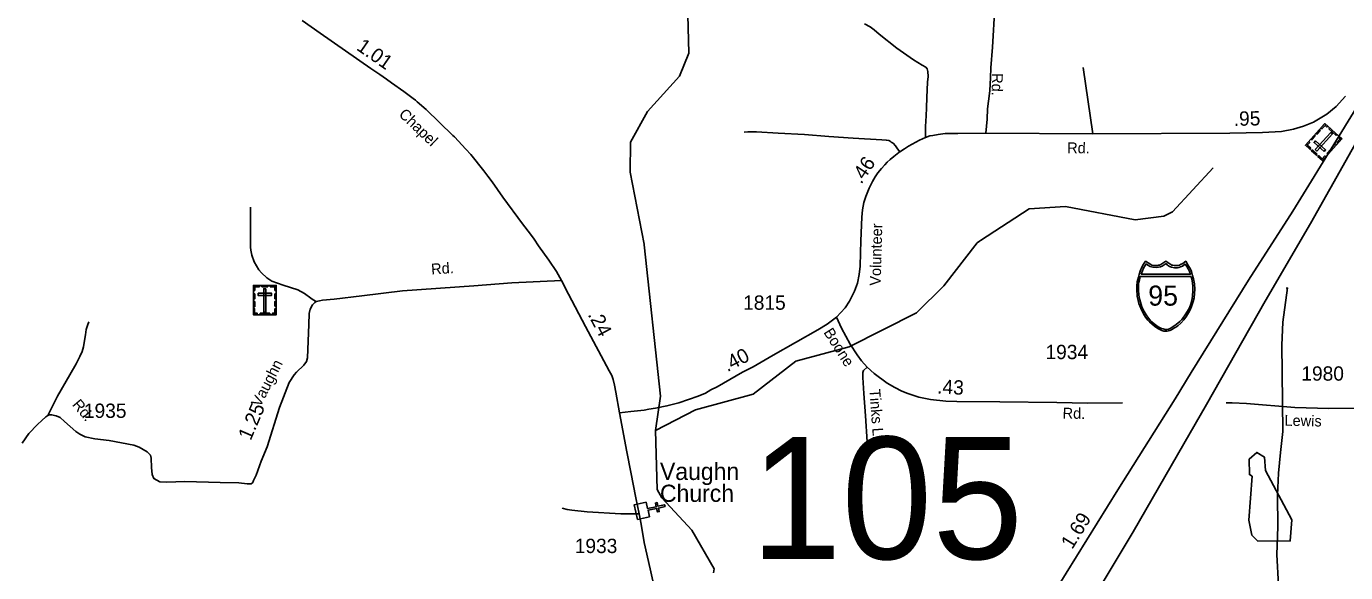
# Model space of a CAD drawing. Extents: x 2220236 to 2384410, y 720751 to 894131.
# Drawn here: x 2299448 to 2310967, y 772170 to 776939 of the extents above; entities that cross this region are included whole.
import ezdxf

# ---------------------------------------------------------------- set-up
doc = ezdxf.new("R2010")
doc.units = 0
for name, color, linetype in [('Exist Cultural Cemetery CELL', 7, 'Continuous'), ('Exist Cultural Church CELL', 7, 'Continuous'), ('Exist Cultural Church Label', 7, 'Continuous'), ('Exist Hydrographic Creek Single Shore', 7, 'Continuous'), ('Exist Hydrographic Misc Water Feature', 7, 'Continuous'), ('Exist Hydrographic Pond Under 1500 Sq Ft', 7, 'Continuous'), ('Exist Road Non-System Type 51', 7, 'Continuous'), ('Exist Road Non-System Type 51 Label', 7, 'Continuous'), ('Exist Road Primary Interstate Divided Center Attributed', 7, 'Continuous'), ('Exist Road Primary Interstate Mileage Hundredths English Label', 7, 'Continuous'), ('Exist Road Primary Interstate Shield CELL', 7, 'Continuous'), ('Exist Road Primary Interstate Shield Number Label', 7, 'Continuous'), ('Exist Road Secondary Mileage Hundredths English Label', 7, 'Continuous'), ('Exist Road Secondary Structure Standard Bridge Number Label', 7, 'Continuous'), ('Exist Road Secondary Type 20 Attributed', 7, 'Continuous'), ('Exist Road Secondary Type 51 Attributed', 7, 'Continuous'), ('Exist Road Secondary Type 51 Label', 7, 'Continuous'), ('Exist Road Secondary Type 51 Number Label', 7, 'Continuous')]:
    doc.layers.add(name, color=color, linetype=linetype)

msp = doc.modelspace()

# ---------------------------------------------------------------- linework, layer by layer
at = {"layer": 'Exist Cultural Cemetery CELL'}
for points in [[(2310764, 775768), (2310616, 775901), (2310786, 776090), (2310934, 775957)], [(2310702, 775863), (2310716, 775850), (2310852, 776001), (2310838, 776013)], [(2310746, 776029), (2310717, 775997), (2310709, 776005), (2310738, 776037)], [(2310811, 776068), (2310803, 776060), (2310787, 776074), (2310760, 776044), (2310751, 776052), (2310786, 776090)], [(2310884, 775987), (2310821, 776044), (2310828, 776052), (2310891, 775996)], [(2310645, 775934), (2310653, 775926), (2310632, 775902), (2310662, 775875), (2310654, 775867), (2310616, 775901)], [(2310702, 775980), (2310673, 775948), (2310665, 775956), (2310694, 775988)], [(2310779, 775846), (2310791, 775860), (2310704, 775939), (2310691, 775925)], [(2310887, 775905), (2310858, 775873), (2310850, 775881), (2310879, 775913)], [(2310909, 775979), (2310902, 775971), (2310918, 775956), (2310891, 775926), (2310899, 775919), (2310934, 775957)], [(2310709, 775818), (2310670, 775852), (2310678, 775861), (2310716, 775826)], [(2310793, 775800), (2310784, 775808), (2310763, 775784), (2310732, 775811), (2310725, 775803), (2310764, 775768)], [(2310842, 775855), (2310813, 775823), (2310805, 775831), (2310834, 775863)], [(2301430, 774677), (2301629, 774677), (2301629, 774422), (2301430, 774422)], [(2301430, 774634), (2301442, 774634), (2301442, 774666), (2301482, 774666), (2301482, 774677), (2301430, 774677)], [(2301504, 774677), (2301556, 774677), (2301556, 774666), (2301504, 774666)], [(2301539, 774648), (2301521, 774648), (2301521, 774445), (2301539, 774445)], [(2301629, 774634), (2301618, 774634), (2301618, 774666), (2301577, 774666), (2301577, 774677), (2301629, 774677)], [(2301430, 774559), (2301430, 774603), (2301442, 774603), (2301442, 774559)], [(2301430, 774492), (2301430, 774536), (2301442, 774536), (2301442, 774492)], [(2301471, 774609), (2301471, 774590), (2301589, 774590), (2301589, 774609)], [(2301618, 774561), (2301618, 774604), (2301629, 774604), (2301629, 774561)], [(2301618, 774495), (2301618, 774538), (2301629, 774538), (2301629, 774495)], [(2301463, 774422), (2301463, 774434), (2301441, 774434), (2301441, 774474), (2301430, 774474), (2301430, 774422)], [(2301488, 774434), (2301573, 774434), (2301573, 774422), (2301488, 774422)], [(2301596, 774422), (2301596, 774434), (2301618, 774434), (2301618, 774474), (2301629, 774474), (2301629, 774422)]]:
    msp.add_lwpolyline(points, close=True, dxfattribs=at)
at = {"layer": 'Exist Cultural Church CELL'}
msp.add_lwpolyline([(2304860, 772786), (2304872, 772730), (2304947, 772746), (2304940, 772778), (2304956, 772781), (2304962, 772750), (2305021, 772763), (2305025, 772747), (2304966, 772734), (2304973, 772703), (2304957, 772700), (2304950, 772731), (2304876, 772714), (2304888, 772658), (2304784, 772635), (2304756, 772763)], close=True, dxfattribs=at)
at = {"layer": 'Exist Hydrographic Creek Single Shore'}
for points in [[(2304841, 775037), (2304719, 775667), (2304724, 775927), (2304871, 776195), (2305151, 776505), (2305232, 776706), (2305218, 777263), (2305291, 777473), (2305478, 777858), (2305851, 778080), (2306040, 778271), (2306253, 778615), (2306484, 778811), (2306799, 778998), (2306948, 779040), (2307573, 778997), (2307766, 778900), (2308149, 778879), (2308324, 778962), (2308523, 778957)], [(2304941, 773412), (2304984, 773712), (2304842, 775032)], [(2310380, 772062), (2310366, 772327), (2310374, 772571), (2310371, 772847), (2310380, 773039), (2310399, 773220), (2310419, 773401), (2310416, 773655), (2310413, 773921), (2310410, 774155), (2310419, 774357), (2310458, 774655), (2310448, 774654)], [(2305446, 772169), (2305454, 772202), (2305258, 772542), (2304997, 772824), (2304955, 772897), (2304941, 773412)]]:
    msp.add_lwpolyline(points, dxfattribs=at)
at = {"layer": 'Exist Hydrographic Misc Water Feature'}
msp.add_line((2307749, 775049), (2307771, 775063), dxfattribs=at)
for points in [[(2307779, 775069), (2308204, 775347), (2308521, 775366), (2309130, 775250), (2309380, 775283), (2309454, 775319), (2309809, 775704)], [(2304842, 775032), (2304841, 775037)], [(2304941, 773412), (2305289, 773590), (2305795, 773729), (2306167, 774017), (2306632, 774141), (2307221, 774437), (2307459, 774673), (2307749, 775049)], [(2307771, 775063), (2307779, 775069)]]:
    msp.add_lwpolyline(points, dxfattribs=at)
at = {"layer": 'Exist Hydrographic Pond Under 1500 Sq Ft'}
msp.add_lwpolyline([(2310200, 772445), (2310149, 772496), (2310122, 772629), (2310152, 773011), (2310127, 773026), (2310125, 773161), (2310191, 773219), (2310258, 773179), (2310267, 773062), (2310498, 772631), (2310483, 772447), (2310200, 772445)], dxfattribs=at)
at = {"layer": 'Exist Road Non-System Type 51'}
msp.add_line((2308760, 776001), (2308675, 776581), dxfattribs=at)
for points in [[(2307298, 775969), (2307298, 776065), (2307304, 776157), (2307306, 776228), (2307310, 776319), (2307314, 776385), (2307317, 776453), (2307323, 776501), (2307319, 776545), (2307312, 776568), (2307300, 776584), (2307268, 776599), (2307193, 776647), (2307048, 776749), (2306893, 776870), (2306849, 776910), (2306814, 776935), (2306765, 776960)], [(2305714, 776015), (2305748, 776018), (2305823, 776017), (2306012, 776008), (2306242, 775994), (2306453, 775979), (2306667, 775963), (2306916, 775949), (2306956, 775946), (2306977, 775942), (2306991, 775937), (2307000, 775929), (2307015, 775919), (2307036, 775896), (2307053, 775869), (2307075, 775845)], [(2301977, 774536), (2301952, 774553), (2301931, 774567), (2301876, 774607), (2301819, 774638), (2301689, 774680), (2301591, 774714), (2301546, 774744), (2301500, 774786), (2301478, 774813), (2301437, 774882), (2301415, 774941), (2301408, 774986), (2301406, 775010), (2301406, 775058), (2301405, 775362)], [(2299634, 773541), (2299665, 773599), (2299720, 773710), (2299828, 773897), (2299884, 773992), (2299915, 774056), (2299934, 774102), (2299946, 774140), (2299955, 774198), (2299963, 774247), (2299971, 774293), (2299982, 774327), (2299993, 774360)], [(2306790, 773965), (2306758, 773936), (2306752, 773918), (2306751, 773874), (2306759, 773733), (2306774, 773538), (2306790, 773313), (2306796, 773221)], [(2309018, 773652), (2308712, 773651), (2308445, 773654)], [(2304126, 772734), (2304170, 772720), (2304209, 772714), (2304345, 772702), (2304639, 772684), (2304733, 772684), (2304797, 772684)]]:
    msp.add_lwpolyline(points, dxfattribs=at)
at = {"layer": 'Exist Road Primary Interstate Divided Center Attributed'}
for points in [[(2311453, 776878), (2311350, 776706), (2311169, 776404), (2310909, 775982), (2310506, 775325), (2310120, 774722), (2309617, 773917), (2309477, 773688), (2308979, 772894), (2308528, 772165), (2308303, 771802), (2307636, 770733), (2307136, 769903), (2306871, 769438), (2306782, 769281)], [(2307079, 769254), (2307173, 769409), (2307400, 769774), (2307703, 770250), (2307875, 770521), (2308386, 771328), (2308543, 771581), (2309112, 772527), (2309554, 773295), (2309751, 773639), (2310264, 774540), (2310660, 775218), (2311194, 776164), (2311386, 776502), (2311488, 776681)]]:
    msp.add_lwpolyline(points, dxfattribs=at)
at = {"layer": 'Exist Road Primary Interstate Shield CELL'}
for points in [[(2309396, 774278), (2309406, 774278), (2309418, 774281), (2309431, 774285), (2309445, 774291), (2309466, 774303), (2309483, 774313), (2309502, 774326), (2309528, 774349), (2309554, 774377), (2309577, 774408), (2309595, 774437), (2309611, 774470), (2309625, 774501), (2309636, 774536), (2309643, 774570), (2309646, 774606), (2309649, 774646), (2309646, 774690), (2309638, 774736), (2309631, 774764), (2309620, 774798), (2309611, 774820), (2309590, 774858), (2309571, 774888), (2309544, 774869), (2309526, 774859), (2309515, 774854), (2309504, 774852), (2309484, 774850), (2309471, 774850), (2309459, 774853), (2309449, 774855), (2309441, 774859), (2309396, 774888), (2309352, 774859), (2309343, 774855), (2309333, 774853), (2309324, 774850), (2309309, 774850), (2309297, 774850), (2309285, 774852), (2309276, 774854), (2309266, 774859), (2309220, 774888), (2309203, 774862), (2309188, 774837), (2309173, 774801), (2309163, 774773), (2309157, 774750), (2309148, 774708), (2309144, 774672), (2309143, 774646), (2309148, 774581), (2309155, 774547), (2309162, 774519), (2309186, 774459), (2309204, 774425), (2309219, 774401), (2309241, 774374), (2309253, 774361), (2309297, 774322), (2309327, 774301), (2309351, 774289), (2309363, 774284), (2309380, 774279)], [(2309226, 774867), (2309215, 774850), (2309202, 774827), (2309192, 774804), (2309182, 774777), (2309613, 774777), (2309603, 774800), (2309592, 774822), (2309581, 774843), (2309567, 774863), (2309543, 774847), (2309526, 774839), (2309511, 774834), (2309499, 774832), (2309481, 774830), (2309473, 774831), (2309447, 774836), (2309429, 774844), (2309412, 774855), (2309399, 774868), (2309365, 774847), (2309350, 774840), (2309332, 774836), (2309313, 774833), (2309284, 774836), (2309260, 774844), (2309241, 774855)], [(2309616, 774756), (2309620, 774744), (2309627, 774717), (2309630, 774696), (2309634, 774672), (2309632, 774631), (2309630, 774588), (2309626, 774563), (2309621, 774540), (2309614, 774515), (2309603, 774481), (2309587, 774452), (2309567, 774420), (2309545, 774392), (2309536, 774381), (2309518, 774362), (2309486, 774336), (2309462, 774319), (2309434, 774302), (2309420, 774296), (2309403, 774292), (2309390, 774293), (2309373, 774298), (2309360, 774301), (2309330, 774317), (2309306, 774333), (2309266, 774366), (2309245, 774391), (2309225, 774420), (2309207, 774450), (2309188, 774490), (2309175, 774530), (2309165, 774573), (2309158, 774626), (2309157, 774658), (2309159, 774689), (2309162, 774705), (2309166, 774725), (2309174, 774756)]]:
    msp.add_lwpolyline(points, close=True, dxfattribs=at)
at = {"layer": 'Exist Road Secondary Type 20 Attributed'}
msp.add_lwpolyline([(2304119, 774721), (2303686, 774699), (2303356, 774674), (2302733, 774630), (2302378, 774587), (2302134, 774558), (2302034, 774548), (2302006, 774542), (2301977, 774536), (2301967, 774529), (2301947, 774507), (2301927, 774471), (2301918, 774433), (2301913, 774336), (2301902, 774044), (2301893, 774014), (2301871, 773982), (2301807, 773921), (2301785, 773898), (2301741, 773829), (2301659, 773613), (2301550, 773269), (2301497, 773142), (2301453, 773022), (2301432, 772973), (2301425, 772956), (2301410, 772944), (2301375, 772944), (2301304, 772953), (2301139, 772956), (2300830, 772965), (2300675, 772960), (2300612, 772964), (2300586, 772977), (2300562, 772991), (2300546, 773027), (2300541, 773087), (2300537, 773169), (2300532, 773195), (2300502, 773224), (2300469, 773246), (2300432, 773266), (2300385, 773284), (2300171, 773323), (2300047, 773337), (2299961, 773355), (2299915, 773378), (2299879, 773402), (2299782, 773489), (2299742, 773523), (2299708, 773540), (2299668, 773549), (2299646, 773547), (2299634, 773541), (2299619, 773531), (2299582, 773499), (2299545, 773464), (2299470, 773386), (2299410, 773301)], dxfattribs=at)
at = {"layer": 'Exist Road Secondary Type 51 Attributed'}
for points in [[(2306813, 781168), (2307748, 779827), (2307813, 779709), (2307834, 779659), (2307886, 779490), (2307906, 779328), (2307918, 778692), (2307918, 778487), (2307916, 778397), (2307918, 778332), (2307923, 778264), (2307928, 777855), (2307919, 777681), (2307918, 777343), (2307908, 777138), (2307904, 777108), (2307882, 776758), (2307868, 776578), (2307866, 776489), (2307859, 776378), (2307857, 776354), (2307841, 776218), (2307838, 776130), (2307826, 776008)], [(2301856, 776991), (2302013, 776879), (2302456, 776571), (2302533, 776520), (2302593, 776478), (2302635, 776446), (2302744, 776370), (2302826, 776308), (2302845, 776294), (2302861, 776279), (2302940, 776213), (2303170, 775987), (2303186, 775975), (2303286, 775867), (2303328, 775819), (2303441, 775679), (2303476, 775631), (2303516, 775582), (2303609, 775449), (2303780, 775215), (2303850, 775126), (2303881, 775080), (2303918, 775022), (2304009, 774899), (2304076, 774799), (2304119, 774721)], [(2307826, 776008), (2308760, 776001), (2309957, 776007), (2310242, 776012), (2310407, 776022), (2310511, 776042), (2310600, 776069), (2310686, 776104), (2310804, 776173), (2310885, 776240), (2310967, 776330)], [(2306521, 774399), (2306596, 774481), (2306634, 774539), (2306679, 774627), (2306704, 774697), (2306719, 774773), (2306729, 774845), (2306731, 774961), (2306734, 775066), (2306742, 775274), (2306749, 775336), (2306761, 775401), (2306778, 775455), (2306806, 775526), (2306835, 775584), (2306860, 775625), (2306883, 775659), (2306914, 775699), (2306942, 775731), (2306964, 775754), (2306990, 775778), (2307023, 775803), (2307065, 775838), (2307075, 775845), (2307115, 775870), (2307149, 775893), (2307246, 775947), (2307298, 775969), (2307336, 775982), (2307362, 775986), (2307409, 775995), (2307470, 776003), (2307581, 776005), (2307826, 776008)], [(2304119, 774721), (2304181, 774601), (2304331, 774319), (2304536, 773933), (2304559, 773891), (2304572, 773855), (2304584, 773807), (2304596, 773746), (2304627, 773566)], [(2304627, 773566), (2304725, 773576), (2304841, 773589), (2304883, 773596), (2304940, 773605), (2305040, 773626), (2305146, 773653), (2305313, 773710), (2305377, 773737), (2305425, 773766), (2305478, 773792), (2305701, 773919), (2305794, 773968), (2305967, 774069), (2306359, 774289), (2306440, 774340), (2306521, 774399)], [(2306521, 774399), (2306566, 774304), (2306642, 774165), (2306703, 774071), (2306741, 774019), (2306790, 773965), (2306850, 773910), (2306964, 773823), (2307031, 773785), (2307092, 773755), (2307143, 773733), (2307241, 773701), (2307341, 773682), (2307475, 773668), (2307571, 773663), (2307946, 773661), (2308445, 773654)], [(2312403, 773619), (2312025, 773602), (2311449, 773603), (2311132, 773607), (2310820, 773604), (2310524, 773611), (2310102, 773646), (2309976, 773652), (2309923, 773653)], [(2304627, 773566), (2304691, 773224), (2304727, 773048), (2304769, 772823), (2304797, 772684), (2304815, 772592), (2304843, 772434), (2304881, 772268), (2304925, 772061), (2304959, 771892), (2304995, 771736), (2305028, 771574), (2305058, 771421), (2305075, 771361), (2305126, 771218), (2305257, 770865), (2305470, 770349), (2305588, 770061), (2305640, 769918), (2305667, 769834), (2305708, 769693), (2305756, 769482), (2305770, 769357)]]:
    msp.add_lwpolyline(points, dxfattribs=at)

# ---------------------------------------------------------------- texts
at = {"layer": 'Exist Cultural Church Label'}
for s, p in [('Vaughn', (2304980, 772979)), ('Church', (2304980, 772788))]:
    msp.add_text(s, height=150, dxfattribs=at).set_placement(p)
at = {"layer": 'Exist Road Non-System Type 51 Label'}
msp.add_text('Tinks Ln', height=95, rotation=274.1777, dxfattribs=at).set_placement((2306808, 773770))
at = {"layer": 'Exist Road Primary Interstate Mileage Hundredths English Label'}
msp.add_text('1.69', height=125, rotation=58.2344, dxfattribs=at).set_placement((2308579, 772367))
at = {"layer": 'Exist Road Primary Interstate Shield Number Label'}
msp.add_text('95', height=175, dxfattribs=at).set_placement((2309243, 774501))
at = {"layer": 'Exist Road Secondary Mileage Hundredths English Label'}
for s, rotation, p in [('1.01', 325.162, (2302322, 776740)), ('.95', 1.1541, (2309991, 776070)), ('.46', 56.3276, (2306738, 775555)), ('.24', 298.0056, (2304347, 774423)), ('.40', 27.6833, (2305568, 773919)), ('.43', 357.0801, (2307398, 773734)), ('1.25', 66.7625, (2301406, 773317))]:
    msp.add_text(s, height=125, rotation=rotation, dxfattribs=at).set_placement(p)
at = {"layer": 'Exist Road Secondary Structure Standard Bridge Number Label'}
msp.add_text('105', height=1066.3, dxfattribs=at).set_placement((2305772, 772289))
at = {"layer": 'Exist Road Secondary Type 51 Label'}
for s, rotation, p in [('Rd.', 269.0318, (2307879, 776531)), ('Chapel', 316.3654, (2302693, 776163)), ('Rd.', 359.4088, (2308535, 775832)), ('Volunteer', 88.4885, (2306907, 774674)), ('Rd.', 3.8864, (2302985, 774772)), ('Boone', 302.3358, (2306405, 774268)), ('Vaughn', 62.9417, (2301490, 773609)), ('Rd.', 310.2004, (2299843, 773634)), ('Rd.', 359.1772, (2308495, 773515)), ('Lewis', 358.6833, (2310432, 773453))]:
    msp.add_text(s, height=95, rotation=rotation, dxfattribs=at).set_placement(p)
at = {"layer": 'Exist Road Secondary Type 51 Number Label'}
for s, p in [('1815', (2305706, 774465)), ('1934', (2308346, 774034)), ('1980', (2310580, 773846)), ('1935', (2299950, 773521)), ('1933', (2304236, 772341))]:
    msp.add_text(s, height=125, dxfattribs=at).set_placement(p)

doc.saveas('drawing.dxf')
